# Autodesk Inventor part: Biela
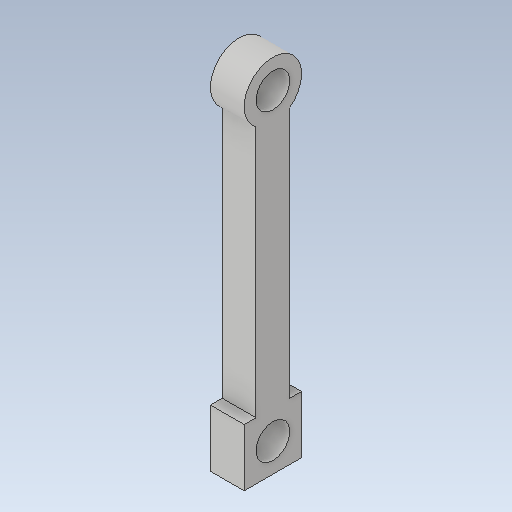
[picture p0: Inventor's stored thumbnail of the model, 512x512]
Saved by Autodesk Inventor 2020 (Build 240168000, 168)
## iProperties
Created: 2019-09
Part Number: Biela
Material: Generic
Document SubType Name: Modeling
Designer: user
Density: 1 g/cm^3
Appearance: Default
Mass: 10.9409 g
Surface Area: 53.1619 cm^2
Volume: 10.9409 cm^3
Author: user
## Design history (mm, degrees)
sketch "Sketch1"
  geometry: L1 (8.5, 8.5)-(-8.5, 8.5); L2 (-8.5, 8.5)-(-8.5, -8.5); L3 (-8.5, -8.5)-(8.5, -8.5); L4 (84.41, -5)-(8.5, -5); L5 (84.41, 5)-(8.5, 5); L6 (8.5, -8.5)-(8.5, -5); L7 (8.5, 5)-(8.5, 8.5); C1 r 5 at (0, 0); C2 r 5 at (90, 0); A1 r 7.5 centre (90, 0) between (84.41, -5) and (84.41, 5); 4 further points
  constraints: 14 end point, 3 centre point, 3 parallel, 3 perpendicular, 2 coincident, 2 midpoint, 2 point on circle, 1 horizontal, 1 horizontal alignment, 1 tangent, 1 vertical alignment
  dimensions: "d0" = 90 distance of C2.centre point (0, 0); "d1" = 10 diameter of C1; "d3" = 17 distance of L3.end L2.end; "d4" = 17 distance of L2.end L1.end; "d5" = 10 diameter of C2; "d6" = 15 diameter of A1
extrude "Extrusion1" new body sketch "Sketch1" distance "d9" = 10; taper "d10" = 0 deg
sketch "Sketch2"
  geometry: C1 r 5 at (0, 90) reference; C2 r 8.5 at (0, 90); C3 r 6.403 at (0, 90); 1 further point
  constraints: 2 centre point, 2 coincident
  dimensions: "d11" = 17 diameter of C2
extrude "Extrusion2" join sketch "Sketch2" distance "d12" = 10; taper "d13" = 0 deg
body "Solid1"
